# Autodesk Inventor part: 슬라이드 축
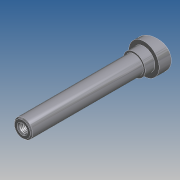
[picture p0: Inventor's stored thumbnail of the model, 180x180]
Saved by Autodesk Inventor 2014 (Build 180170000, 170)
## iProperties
Created: 2012-05
Part Number: 슬라이드 축
Document SubType Name: 모델링
Designer: SeoGD™
Mass: 21.5729 g
Surface Area: 67.586 cm^2
Volume: 21.5729 cm^3
Density: 1 g/cm^3
Material: 강철, 연강
Appearance: 강철
변환 표준: STEP AP214IS
파일 이름: C:\Users\SeoGD\Desktop\?쒗뿕\異?stp
전처리기: Build: 253, Release: 2010 SP1 - Date: Wed 07/29/2009
전송 단위: 밀리미터
불확실성: 0.01
Author: SeoGD™
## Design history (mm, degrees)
sketch "스케치1"
  geometry: L1 (0, 100)-(7.5, 100); L2 (7.5, 100)-(7.5, 0); L3 (7.5, 0)-(12.5, 0); L4 (12.5, 0)-(12.5, -17); L5 (12.5, -17)-(0, -17); L6 (0, -17)-(0, 100); 1 further point
  constraints: 12 end point, 2 parallel, 2 point on line, 1 perpendicular, 1 vertical
  dimensions: "d0" = 100 distance from line of L1 point (0, 0); "d1" = 15 diameter of L2 L6; "d2" = 25 diameter of L4 L6; "d3" = 17 distance of L3.end L4.end
revolve "회전1" sketch "스케치1" stored, may be unused: angle "d4" = 90 deg
sketch "스케치2"
  geometry: L1 (12.5, 0)-(12.5, -17) reference; L2 (-12.5, -17)-(12.5, -17) reference; L3 (-12.5, 0)-(-12.5, -17) reference; L4 (12.5, -5)-(-12.5, -11.699); L5 (-12.5, 0)-(12.5, 0) reference; 1 further point
  constraints: 2 end point, 2 point on line
  dimensions: "d5" = 75 deg angle of L1 L4; "d6" = 5 distance from line of L4.start L5
extrude "돌출1" cut sketch "스케치2" stored distance "d7" = 10; taper "d8" = 0 deg
chamfer "모따기1" distance "d9" = 1; stored, may be unused: second distance "d10" = 2, angle "d11" = 45 deg
fillet "모깎기1" dims "d12" = 0.5
hole "구멍1" diameter "d15" = 6.647; stored, may be unused: countersink angle "d19" = 90 deg, drill point angle "d21" = 118 deg; dims "d13" = 10, "d14" = 10, "d16" = 17, "d17" = 4, "d18" = 2, "d20" = 20
chamfer "모따기2" distance "d22" = 1; stored, may be unused: second distance "d23" = 2, angle "d24" = 45 deg
sketch "스케치3"
  geometry: C1 r 9 at (0, 0); 1 further point
  constraints: 1 centre point, 1 coincident
  dimensions: "d25" = 18 diameter of C1
extrude "돌출2" join sketch "스케치3" distance "d26" = 8; taper "d27" = 0 deg
node "솔리드1"
node "솔리드 본체"
node "곡면 본체"
node "솔리드2"
